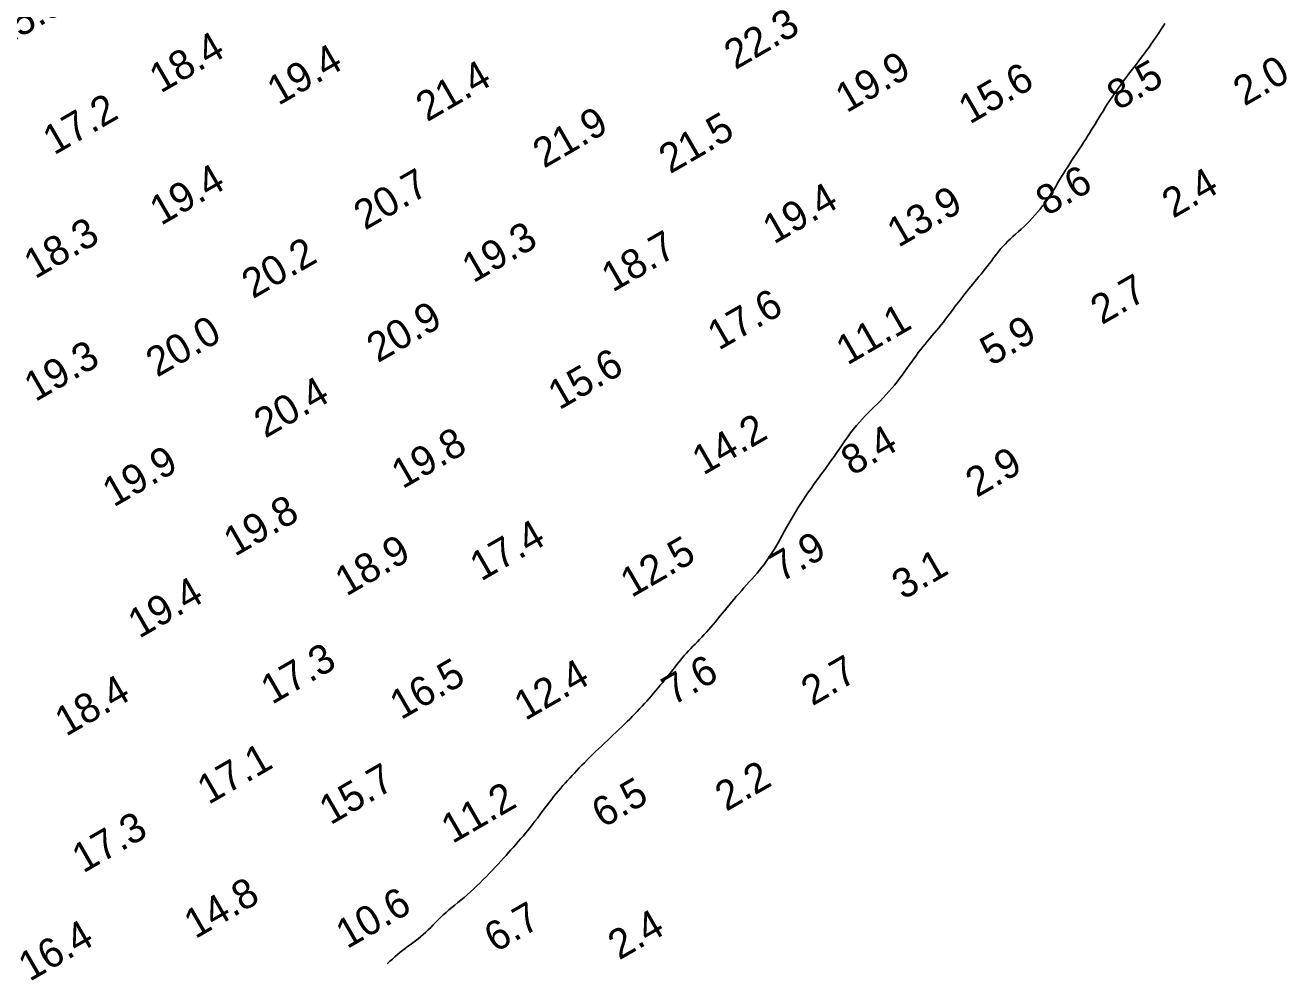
# Model space of a CAD drawing. Extents: x 3024098 to 3056816, y 418252 to 509144.
# Drawn here: x 3028058.7 to 3028273.3, y 424932.3 to 425091.7 of the extents above; entities that cross this region are included whole.
import ezdxf

# ---------------------------------------------------------------- set-up
doc = ezdxf.new("R2010")
doc.units = 0
doc.layers.add('V-CHAN-CONT-EL10', color=7, linetype='Continuous')
doc.layers.add('V-TOPO-SOUN-0911', color=7, linetype='Continuous')

msp = doc.modelspace()

# ---------------------------------------------------------------- linework, layer by layer
at = {"layer": 'V-CHAN-CONT-EL10'}
msp.add_lwpolyline([(3028252.61, 425091.99), (3028252.24, 425091.43), (3028251.86, 425090.87), (3028251.48, 425090.3), (3028251.1, 425089.73), (3028250.71, 425089.16), (3028250.31, 425088.58), (3028249.9, 425088), (3028249.47, 425087.42), (3028249.05, 425086.83), (3028248.61, 425086.25), (3028248.18, 425085.67), (3028247.74, 425085.09), (3028247.3, 425084.51), (3028246.86, 425083.94), (3028246.43, 425083.37), (3028246, 425082.81), (3028245.58, 425082.25), (3028245.16, 425081.69), (3028244.75, 425081.13), (3028244.34, 425080.57), (3028243.95, 425080), (3028243.56, 425079.43), (3028243.17, 425078.85), (3028242.8, 425078.27), (3028242.43, 425077.69), (3028242.07, 425077.1), (3028241.72, 425076.53), (3028241.37, 425075.96), (3028241.04, 425075.4), (3028240.71, 425074.86), (3028240.39, 425074.34), (3028240.07, 425073.83), (3028239.76, 425073.33), (3028239.45, 425072.83), (3028239.14, 425072.34), (3028238.82, 425071.85), (3028238.5, 425071.35), (3028238.17, 425070.84), (3028237.83, 425070.33), (3028237.48, 425069.8), (3028237.13, 425069.26), (3028236.77, 425068.72), (3028236.41, 425068.17), (3028236.06, 425067.61), (3028235.7, 425067.06), (3028235.36, 425066.5), (3028235.02, 425065.94), (3028234.68, 425065.38), (3028234.35, 425064.82), (3028234.02, 425064.27), (3028233.68, 425063.71), (3028233.33, 425063.16), (3028232.97, 425062.6), (3028232.6, 425062.05), (3028232.2, 425061.51), (3028231.8, 425060.97), (3028231.37, 425060.43), (3028230.94, 425059.9), (3028230.49, 425059.38), (3028230.04, 425058.88), (3028229.57, 425058.39), (3028229.1, 425057.92), (3028228.63, 425057.46), (3028228.15, 425057.02), (3028227.68, 425056.59), (3028227.21, 425056.17), (3028226.75, 425055.76), (3028226.31, 425055.35), (3028225.88, 425054.94), (3028225.47, 425054.53), (3028225.08, 425054.11), (3028224.71, 425053.69), (3028224.35, 425053.26), (3028224.01, 425052.83), (3028223.68, 425052.4), (3028223.35, 425051.96), (3028223.02, 425051.53), (3028222.69, 425051.09), (3028222.35, 425050.66), (3028222.01, 425050.23), (3028221.67, 425049.79), (3028221.32, 425049.36), (3028220.97, 425048.93), (3028220.62, 425048.51), (3028220.27, 425048.09), (3028219.92, 425047.66), (3028219.58, 425047.24), (3028219.24, 425046.83), (3028218.9, 425046.41), (3028218.56, 425045.98), (3028218.22, 425045.55), (3028217.88, 425045.11), (3028217.53, 425044.66), (3028217.17, 425044.19), (3028216.81, 425043.71), (3028216.44, 425043.22), (3028216.06, 425042.72), (3028215.69, 425042.21), (3028215.3, 425041.71), (3028214.91, 425041.2), (3028214.52, 425040.71), (3028214.13, 425040.22), (3028213.74, 425039.75), (3028213.35, 425039.28), (3028212.96, 425038.83), (3028212.57, 425038.37), (3028212.18, 425037.91), (3028211.79, 425037.45), (3028211.4, 425036.98), (3028211.02, 425036.49), (3028210.64, 425035.99), (3028210.26, 425035.47), (3028209.88, 425034.94), (3028209.49, 425034.4), (3028209.11, 425033.85), (3028208.71, 425033.29), (3028208.31, 425032.73), (3028207.89, 425032.17), (3028207.47, 425031.6), (3028207.03, 425031.04), (3028206.58, 425030.48), (3028206.13, 425029.93), (3028205.66, 425029.38), (3028205.18, 425028.85), (3028204.7, 425028.32), (3028204.21, 425027.8), (3028203.71, 425027.29), (3028203.2, 425026.8), (3028202.69, 425026.3), (3028202.18, 425025.8), (3028201.67, 425025.28), (3028201.15, 425024.75), (3028200.64, 425024.19), (3028200.13, 425023.6), (3028199.63, 425022.98), (3028199.13, 425022.33), (3028198.64, 425021.67), (3028198.16, 425020.99), (3028197.69, 425020.31), (3028197.24, 425019.65), (3028196.79, 425019), (3028196.37, 425018.38), (3028195.96, 425017.79), (3028195.56, 425017.23), (3028195.17, 425016.69), (3028194.79, 425016.17), (3028194.41, 425015.65), (3028194.03, 425015.13), (3028193.64, 425014.6), (3028193.24, 425014.05), (3028192.83, 425013.48), (3028192.41, 425012.89), (3028191.98, 425012.28), (3028191.54, 425011.65), (3028191.11, 425011), (3028190.67, 425010.34), (3028190.24, 425009.66), (3028189.82, 425008.98), (3028189.41, 425008.29), (3028189, 425007.6), (3028188.61, 425006.91), (3028188.23, 425006.22), (3028187.85, 425005.55), (3028187.49, 425004.89), (3028187.13, 425004.26), (3028186.79, 425003.64), (3028186.45, 425003.06), (3028186.12, 425002.5), (3028185.79, 425001.97), (3028185.46, 425001.45), (3028185.13, 425000.94), (3028184.78, 425000.44), (3028184.42, 424999.95), (3028184.04, 424999.46), (3028183.64, 424998.96), (3028183.22, 424998.47), (3028182.79, 424997.97), (3028182.35, 424997.47), (3028181.9, 424996.97), (3028181.45, 424996.47), (3028181, 424995.97), (3028180.55, 424995.47), (3028180.12, 424994.97), (3028179.69, 424994.48), (3028179.27, 424993.99), (3028178.86, 424993.51), (3028178.46, 424993.02), (3028178.06, 424992.54), (3028177.67, 424992.07), (3028177.28, 424991.6), (3028176.89, 424991.13), (3028176.51, 424990.66), (3028176.13, 424990.2), (3028175.75, 424989.75), (3028175.38, 424989.3), (3028175, 424988.86), (3028174.62, 424988.43), (3028174.24, 424988.01), (3028173.85, 424987.6), (3028173.46, 424987.2), (3028173.08, 424986.8), (3028172.69, 424986.41), (3028172.32, 424986.03), (3028171.94, 424985.64), (3028171.58, 424985.26), (3028171.23, 424984.88), (3028170.89, 424984.49), (3028170.56, 424984.11), (3028170.23, 424983.72), (3028169.91, 424983.33), (3028169.59, 424982.93), (3028169.27, 424982.52), (3028168.95, 424982.1), (3028168.61, 424981.68), (3028168.26, 424981.24), (3028167.91, 424980.8), (3028167.54, 424980.35), (3028167.17, 424979.89), (3028166.79, 424979.44), (3028166.41, 424978.98), (3028166.02, 424978.52), (3028165.63, 424978.06), (3028165.24, 424977.61), (3028164.85, 424977.16), (3028164.46, 424976.71), (3028164.06, 424976.27), (3028163.66, 424975.83), (3028163.25, 424975.39), (3028162.84, 424974.95), (3028162.42, 424974.52), (3028161.99, 424974.08), (3028161.56, 424973.64), (3028161.12, 424973.2), (3028160.66, 424972.76), (3028160.2, 424972.31), (3028159.73, 424971.86), (3028159.25, 424971.41), (3028158.77, 424970.95), (3028158.27, 424970.48), (3028157.77, 424970.01), (3028157.26, 424969.53), (3028156.75, 424969.05), (3028156.24, 424968.57), (3028155.74, 424968.1), (3028155.25, 424967.62), (3028154.77, 424967.15), (3028154.3, 424966.68), (3028153.85, 424966.22), (3028153.41, 424965.77), (3028152.98, 424965.32), (3028152.56, 424964.88), (3028152.15, 424964.44), (3028151.75, 424964.01), (3028151.36, 424963.58), (3028150.97, 424963.16), (3028150.59, 424962.73), (3028150.21, 424962.31), (3028149.83, 424961.88), (3028149.45, 424961.44), (3028149.07, 424960.99), (3028148.68, 424960.52), (3028148.29, 424960.03), (3028147.9, 424959.52), (3028147.5, 424958.99), (3028147.09, 424958.45), (3028146.68, 424957.9), (3028146.27, 424957.34), (3028145.86, 424956.79), (3028145.45, 424956.24), (3028145.04, 424955.71), (3028144.63, 424955.19), (3028144.23, 424954.69), (3028143.82, 424954.2), (3028143.42, 424953.72), (3028143.01, 424953.25), (3028142.6, 424952.78), (3028142.19, 424952.32), (3028141.78, 424951.85), (3028141.36, 424951.38), (3028140.94, 424950.91), (3028140.52, 424950.43), (3028140.08, 424949.95), (3028139.63, 424949.46), (3028139.18, 424948.95), (3028138.7, 424948.45), (3028138.21, 424947.93), (3028137.71, 424947.4), (3028137.19, 424946.86), (3028136.66, 424946.32), (3028136.12, 424945.79), (3028135.57, 424945.25), (3028135.02, 424944.73), (3028134.47, 424944.23), (3028133.93, 424943.74), (3028133.38, 424943.28), (3028132.85, 424942.83), (3028132.32, 424942.4), (3028131.81, 424941.98), (3028131.3, 424941.57), (3028130.81, 424941.16), (3028130.33, 424940.75), (3028129.86, 424940.33), (3028129.41, 424939.91), (3028128.97, 424939.48), (3028128.55, 424939.05), (3028128.13, 424938.62), (3028127.71, 424938.2), (3028127.3, 424937.78), (3028126.88, 424937.38), (3028126.45, 424936.99), (3028126.02, 424936.62), (3028125.57, 424936.26), (3028125.13, 424935.91), (3028124.68, 424935.58), (3028124.23, 424935.25), (3028123.78, 424934.92), (3028123.34, 424934.59), (3028122.9, 424934.25), (3028122.47, 424933.91), (3028122.04, 424933.55), (3028121.62, 424933.19), (3028121.19, 424932.81), (3028120.74, 424932.42), (3028120.28, 424932.01)], dxfattribs=at)

# ---------------------------------------------------------------- texts
at = {"layer": 'V-TOPO-SOUN-0911'}
for s, p in [('15.3 ', (3028054.62, 425087.69)), ('22.3 ', (3028179.53, 425084.05)), ('18.4 ', (3028081.76, 425080.05)), ('19.4 ', (3028101.8, 425077.95)), ('21.4 ', (3028127.1, 425075.19)), ('19.9 ', (3028198.46, 425076.7)), ('15.6 ', (3028219.39, 425074.77)), ('8.5', (3028244.64, 425077.13)), ('2.0', (3028266.12, 425077.85)), ('17.2 ', (3028063.65, 425069.52)), ('21.9 ', (3028146.98, 425067.28)), ('21.5 ', (3028168.43, 425066.33)), ('19.4 ', (3028081.82, 425057.54)), ('20.7 ', (3028116.53, 425056.75)), ('8.6', (3028232.54, 425059.16)), ('2.4', (3028254, 425058.76)), ('19.4 ', (3028186.09, 425054.36)), ('13.9 ', (3028207.25, 425053.8)), ('18.3 ', (3028060.43, 425048.45)), ('19.3 ', (3028134.94, 425047.76)), ('20.2 ', (3028097.47, 425045.07)), ('18.7 ', (3028158.66, 425046.19)), ('2.7', (3028241.86, 425040.65)), ('17.6 ', (3028176.7, 425036.29)), ('20.9 ', (3028118.73, 425034.18)), ('11.1 ', (3028198.57, 425033.77)), ('5.9', (3028223.06, 425033.63)), ('20.0 ', (3028081.18, 425031.72)), ('19.3 ', (3028060.46, 425027.55)), ('15.6 ', (3028149.57, 425026.15)), ('20.4 ', (3028099.57, 425021.35)), ('14.2 ', (3028174.08, 425015.05)), ('19.8 ', (3028122.93, 425012.72)), ('8.4', (3028199.41, 425014.96)), ('19.9 ', (3028073.78, 425009.61)), ('2.9', (3028220.6, 425011.25)), ('19.8 ', (3028094.39, 425001.21)), ('17.4 ', (3028136.28, 424997.01)), ('18.9 ', (3028113.35, 424994.45)), ('12.5 ', (3028161.86, 424994.22)), ('7.9', (3028187.3, 424996.85)), ('3.1', (3028208.05, 424993.85)), ('19.4 ', (3028078.12, 424987.27)), ('17.3 ', (3028100.72, 424976.04)), ('7.6', (3028168.93, 424975.86)), ('2.7', (3028192.62, 424975.79)), ('16.5 ', (3028122.66, 424973.42)), ('12.4 ', (3028143.8, 424973.29)), ('18.4 ', (3028065.68, 424970.6)), ('17.1 ', (3028089.91, 424959)), ('15.7 ', (3028110.66, 424955.54)), ('2.2', (3028177.98, 424957.84)), ('6.5', (3028157.01, 424955.02)), ('11.2 ', (3028131.4, 424952.36)), ('17.3 ', (3028068.6, 424947.34)), ('14.8 ', (3028087.66, 424936.15)), ('10.6 ', (3028113.48, 424934.45)), ('6.7', (3028138.71, 424933.83)), ('16.4 ', (3028059.48, 424928.9)), ('2.4', (3028159.77, 424932.55))]:
    msp.add_text(s, height=5, rotation=30, dxfattribs=at).set_placement(p)

doc.saveas('drawing.dxf')
